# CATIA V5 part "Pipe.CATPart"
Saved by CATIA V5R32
Part number: Pipe
Bounding box of the stored display mesh (mm): x -50 to 50, y 0 to 150, z -50 to 50
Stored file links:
  D:\PROJECTS\Project 2022\CATIA V5 6R 2022\Resources\Part Files\c12_catia_v5_6r2022_prt\c12_catia_v5-6r2022 figr_12-44\Pipe.CATPart
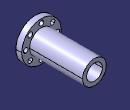
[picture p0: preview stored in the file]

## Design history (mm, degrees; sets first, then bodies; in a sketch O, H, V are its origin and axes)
Body1 (main body)
  Sketch1 on zx-plane, origin (0, 0, 0), H (-1, 0, 0), V (0, 0, 1)
    circle A1 centre (0, 0) radius 50
    point P1 (0, -50)
    circle A2 centre (0, 0) radius 30
    point P2 (0, -30)
    radius A1 = 50
    radius A2 = 30
    coincidence: A1 P1, P1 V, A2 P2, P2 V
  MultiPad1: profile Sketch1, domains (length 150; length 15)
  Sketch2 on face of MultiPad1, origin (0, 150, 0), H (-1, 0, 0), V (0, 0, 1)
    circle A1 centre (0, 0) radius 20
    point P1 (0, -20)
    radius A1 = 20
    coincidence: A1 P1, P1 V
  Pocket1: profile Sketch2, direction (0, -1, 0), through (limit type 3)
  Sketch3 on face of MultiPad1, origin (0, 0, 0), H (1, 0, 0), V (0, 0, 1)
    circle A1 centre (0, -40) radius 6
    point P1 (0, -40)
    radius A1 = 6
    distance H P1 = 40
    coincidence: P1 V
  Pocket2: profile Sketch3, direction (0, 1, 0), through (limit type 3)
  CircPattern1: of Pocket2, instances 8, angular step 45, axis from face of MultiPad1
